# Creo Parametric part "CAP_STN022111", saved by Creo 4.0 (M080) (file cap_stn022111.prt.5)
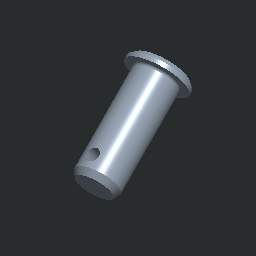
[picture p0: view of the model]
Units: millimeter Kilogram Sec (mmKs); MM, KILOGRAM, SECS
Materials in the file: OCEL

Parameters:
  MFG_WP_MATERIAL = "OCEL"
  NAZOV = "CAP_STN022111"
  NORMA = "STN 01 2111"
  NAZOV_1 = "START_PART_IPM"
  PTC_MATERIAL_NAME = "OCEL"

Other parameters: HMOTNOST, HUSTOTA, HMOTNOST_1, HUSTOTA_1

Created from: C022111.PRT

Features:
  1. datum plane "DTM1"
  2. cut
  3. chamfer
  4. round

Layers: 1, 2, 3, 4, 5, 6, 7, 8, 9, 10, 11, 12, 13, 14, 15, 16, 17, 18, 19, 20, 21, 22, 23, 24, 25, 26, 27, 28, 29, 30, 31, 32

Family table entries: GENERIC, CAP_10X25, CAP_STN022111, value(d_val), 2/,, 2/9, value(i_val), CAP_10X32, CAP_STN022111, !/$, 2/,, 2/@, CAP_10X40, CAP_STN022111, !/$, 2/,, 2/D, CAP_10X45, CAP_STN022111, !/$, 2/,, CAP_10X50, CAP_STN022111, !/$, 2/,, 2/I, CAP_10X56, CAP_STN022111, !/$, 2/,, 2/L, CAP_12X32, CAP_STN022111, !/(, 2/1, 2/@, CAP_12X36, CAP_STN022111, !/(, 2/1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

Surfaces: 5 cylinder, 4 cone, 3 plane, 2 torus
